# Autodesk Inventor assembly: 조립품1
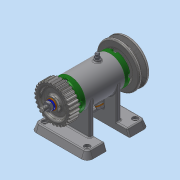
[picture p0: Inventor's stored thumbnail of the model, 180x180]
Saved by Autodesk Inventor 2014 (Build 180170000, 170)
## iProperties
Created: 2016-07
Part Number: 조립품1
Document SubType Name: Assembly
Designer: 406-05
Author: 406-05
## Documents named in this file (16)
- C:\Users\406-05\Desktop\460707V1013\답안조립품.iam
- C:\Users\406-05\Desktop\460707V1013\본체.ipt
- C:\Users\406-05\Desktop\460707V1013\베어링 15 x 32 x 9.ipt
- C:\Users\406-05\Desktop\460707V1013\커버.ipt
- C:\Users\406-05\Desktop\460707V1013\볼트 M4 x 12.ipt
- C:\Users\406-05\Desktop\460707V1013\니플 M 6 x 0.75.ipt
- C:\Users\406-05\Desktop\460707V1013\축.ipt
- C:\Users\406-05\Desktop\460707V1013\키 3 x 3 x 12.ipt
- C:\Users\406-05\Desktop\460707V1013\V벨트풀리.ipt
- C:\Users\406-05\Desktop\460707V1013\스퍼기어.ipt
- C:\Users\406-05\Desktop\460707V1013\와셔 8x17.ipt
- C:\Users\406-05\Desktop\460707V1013\스프링와셔 8.ipt
- C:\Users\406-05\Desktop\460707V1013\너트 M 8.ipt
- C:\Users\406-05\Desktop\460707V1013\와셔 6x11.5.ipt
- C:\Users\406-05\Desktop\460707V1013\볼트 M 6 x 8.ipt
- C:\Users\406-05\Desktop\460707V1013\오일 실 15 25 7.ipt
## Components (11 placed, 3 different names)
1. KS B 2023 6002 - 15 x 32 x 9:1
2. KS B 2023 6002 - 15 x 32 x 9:2
3. V벨트풀리:1
4. ISO 4762 M4 x 12:1
5. ISO 4762 M4 x 12:3
6. ISO 4762 M4 x 12:4
7. ISO 4762 M4 x 12:5
8. ISO 4762 M4 x 12:2
9. ISO 4762 M4 x 12:6
10. ISO 4762 M4 x 12:7
11. ISO 4762 M4 x 12:8
